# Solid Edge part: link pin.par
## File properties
Author: Robert a Rhodes jr
Template: Normal.par
Last saved by: CADCIM
Revision: 13
Application: Solid Edge
Accuracy: 0.99
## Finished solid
Body 1: solid body, 5 faces, 4 edges, 0 vertices.
  Faces by surface: plane 3, cylinder 2
  Edges by curve: circle 4
Bounding box of the edges (mm): 15.000 x 15.000 x 50.000, from (-7.5, -7.5, -22.7536) to (7.5, 7.5, 27.2464).
Cylindrical faces by radius (mm): R5 x1, R7.5 x1
Planar faces by outward normal: +z 1, -z 2
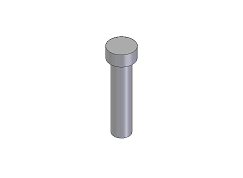
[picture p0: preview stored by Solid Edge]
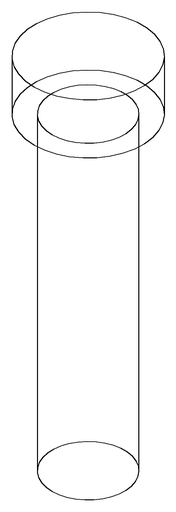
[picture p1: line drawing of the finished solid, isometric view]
